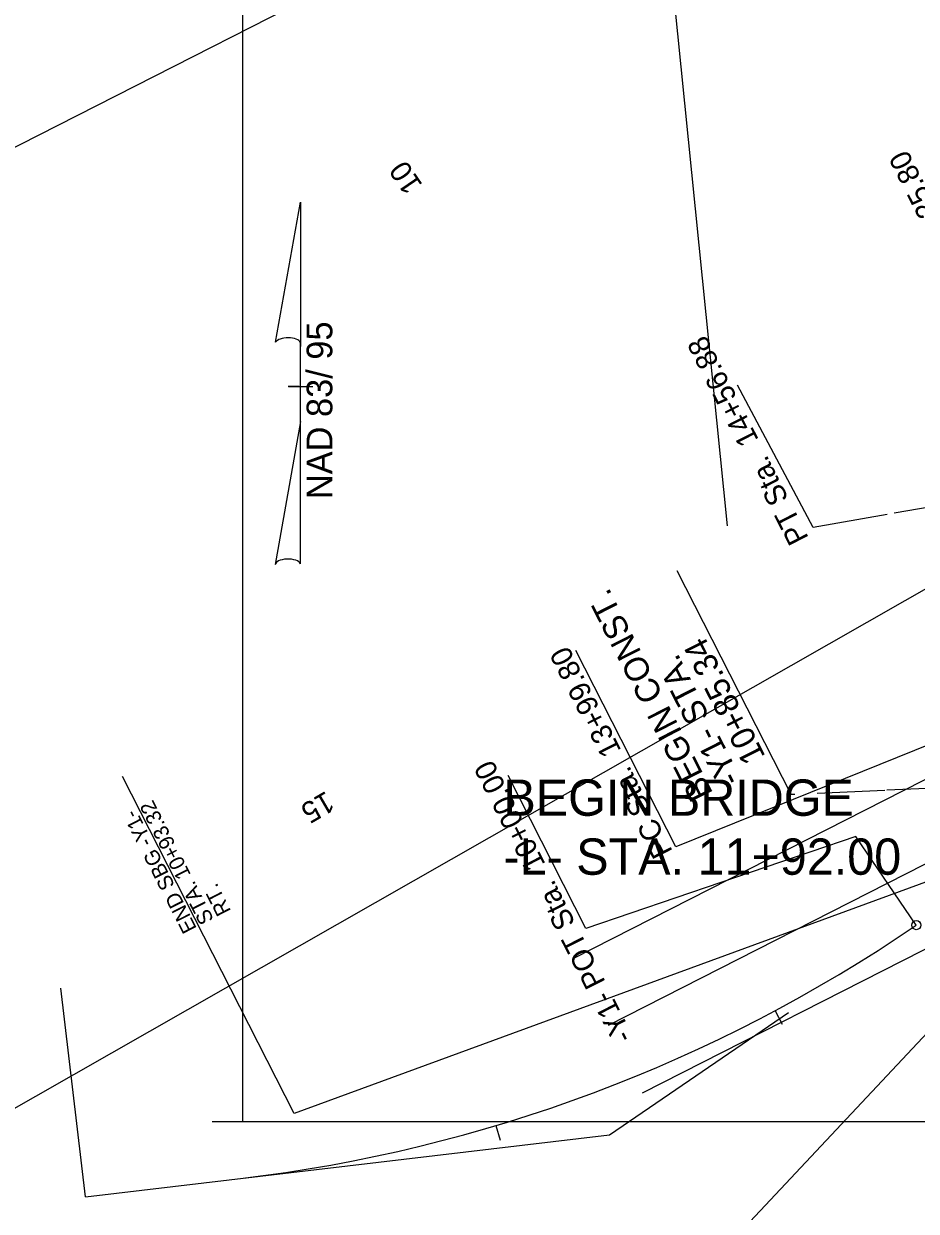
# Model space of a CAD drawing. Extents: x 557583 to 560285, y 513145 to 516544.
# Drawn here: x 558916.3 to 559211.5, y 515428.1 to 515820.8 of the extents above; entities that cross this region are included whole.
import ezdxf

# ---------------------------------------------------------------- set-up
doc = ezdxf.new("R2010")
doc.units = 0
for name, color, linetype in [('Default', 7, 'Continuous'), ('Exist Environmental Wetland Boundary Cogo Comment', 7, 'Continuous'), ('Exist Environmental Wetland Boundary Cogo Point CELL', 7, 'Continuous'), ('Exist Hydro Swamp or Marsh', 7, 'Continuous'), ('Prop Dimension', 7, 'Continuous'), ('Prop DSN Text', 7, 'Continuous'), ('Prop North Arrow NAD83 for Plan Sheets CELL', 7, 'Continuous'), ('Scratch_Level_2', 7, 'Continuous'), ('Scratch_Level_3', 7, 'Continuous'), ('Scratch_Level_4', 7, 'Continuous')]:
    doc.layers.add(name, color=color, linetype=linetype)

msp = doc.modelspace()

# ---------------------------------------------------------------- linework, layer by layer
at = {"layer": 'Default'}
for p, q in [((558988.6, 515880.54), (558988.6, 515457.65)), ((559389.28, 515457.65), (558978.6, 515457.65))]:
    msp.add_line(p, q, dxfattribs=at)
at = {"layer": 'Exist Environmental Wetland Boundary Cogo Point CELL'}
for p, q in [((559177.37, 515654.26), (559152.34, 515701.35)), ((559292.5, 515674.42), (559204.18, 515658.96)), ((559201.9, 515658.56), (559177.37, 515654.26)), ((559131.94, 515548.67), (559098.88, 515613.6)), ((559313.36, 515591.99), (559124.03, 515390.09)), ((559216.64, 515582.81), (559170.76, 515564.32)), ((559102.25, 515521.61), (559076.5, 515572.18)), ((559170.76, 515564.32), (559131.94, 515548.67)), ((559191.49, 515552), (559102.25, 515521.61)), ((559211.5, 515522.74), (559191.49, 515552))]:
    msp.add_line(p, q, dxfattribs=at)
msp.add_circle((559211.5, 515522.74), 1.5, dxfattribs=at)
at = {"layer": 'Exist Hydro Swamp or Marsh'}
for p, q in [((559164.78, 515494.42), (559167.13, 515490.01)), ((559072.45, 515456.44), (559073.88, 515451.65))]:
    msp.add_line(p, q, dxfattribs=at)
at = {"layer": 'Prop Dimension'}
for p, q in [((559170.11, 515565.93), (559132.44, 515639.92)), ((559005.69, 515460.4), (558948.91, 515571.93)), ((559281.95, 515570.9), (559201.81, 515567.34)), ((559294.76, 515566.31), (559005.69, 515460.4)), ((559171.31, 515565.98), (559170.11, 515565.93)), ((559201.15, 515567.31), (559178.67, 515566.31))]:
    msp.add_line(p, q, dxfattribs=at)
at = {"layer": 'Prop DSN Text'}
msp.add_lwpolyline([(558879.66, 516196.55), (559055, 515852.15), (558908.44, 515777.53), (558733.09, 516121.93)], close=True, dxfattribs=at)
at = {"layer": 'Prop North Arrow NAD83 for Plan Sheets CELL'}
for p, q in [((558999.57, 515715.52), (559007.77, 515761.87)), ((559007.82, 515761.87), (559007.77, 515761.87)), ((559007.82, 515761.87), (559007.77, 515761.87)), ((559007.82, 515761.87), (559007.82, 515714.07)), ((559007.82, 515689.27), (559007.82, 515715.47)), ((559007.82, 515714.07), (559007.82, 515715.42)), ((559003.82, 515700.87), (559003.77, 515700.87)), ((559007.37, 515700.87), (559003.82, 515700.87)), ((559003.87, 515700.87), (559011.87, 515700.87)), ((559007.82, 515689.27), (558999.47, 515642.02)), ((559007.87, 515642.22), (559007.82, 515689.27))]:
    msp.add_line(p, q, dxfattribs=at)
for centre, start_param, end_param in [((559003.71, 515715.02), 0.216388, 2.908219), ((559003.71, 515641.85), 0.201328, 3.141593)]:
    msp.add_ellipse(centre, major_axis=(4.23, -0.03), ratio=0.461098, start_param=start_param, end_param=end_param, dxfattribs=at)
at = {"layer": 'Scratch_Level_2'}
for p, q in [((559098.28, 515511.79), (559543.81, 515738.73)), ((559555.17, 515716.41), (559109.6, 515489.55)), ((559120.94, 515467.27), (559566.52, 515694.13))]:
    msp.add_line(p, q, dxfattribs=at)
at = {"layer": 'Scratch_Level_3'}
for p, q in [((559129.15, 515850.4), (559148.98, 515654.78)), ((558936.73, 515432.92), (558928.59, 515501.92)), ((559110.01, 515453.37), (559169.21, 515493.83)), ((558936.73, 515432.92), (559110.01, 515453.37))]:
    msp.add_line(p, q, dxfattribs=at)
msp.add_arc((558929.34, 515935.52), 500, 276.7291, 304.3554, dxfattribs=at)
at = {"layer": 'Scratch_Level_4'}
msp.add_line((559394.6, 515736.6), (558806.81, 515401.49), dxfattribs=at)

# ---------------------------------------------------------------- texts
at = {"layer": 'Default'}
for s, p in [('BEGIN BRIDGE', (559074.95, 515558.9)), ('-L- STA. 11+92.00', (559074.95, 515539.4))]:
    msp.add_text(s, height=12, rotation=360, dxfattribs=at).set_placement(p)
at = {"layer": 'Exist Environmental Wetland Boundary Cogo Comment'}
for s, rotation, p in [('10', 124.3572, (559048.39, 515767.54)), ('15', 210.2524, (559016.3, 515567.3))]:
    msp.add_text(s, height=7, rotation=rotation, dxfattribs=at).set_placement(p)
at = {"layer": 'Exist Environmental Wetland Boundary Cogo Point CELL'}
for s, p in [('POT Sta.  11+25.80', (559246.07, 515705.58)), ('PT Sta.  14+56.88', (559176.04, 515650.75)), ('PC Sta.  13+99.80', (559131.04, 515547.1)), ('-Y1- POT Sta.  10+00.00', (559118.03, 515485.84))]:
    msp.add_text(s, height=7, rotation=116.9819, dxfattribs=at).set_placement(p)
at = {"layer": 'Prop DSN Text'}
for s, height, rotation, p in [('BEGIN CONST.', 8, 116.9819, (559144.41, 515566.33)), (' 10+85.34', 8, 116.9819, (559163.1, 515575.84)), ('-Y1- STA.', 8, 116.9819, (559153.76, 515571.08)), ('STA. 10+93.32', 5, 117.0233, (558979.27, 515524.53)), ('END SBG -Y1-', 5, 117.0233, (558973.63, 515521.65)), ('RT.', 5, 117.0233, (558984.92, 515527.41))]:
    msp.add_text(s, height=height, rotation=rotation, dxfattribs=at).set_placement(p)
at = {"layer": 'Prop North Arrow NAD83 for Plan Sheets CELL'}
msp.add_text('NAD 83/ 95', height=8.5, rotation=90, dxfattribs=at).set_placement((559018.34, 515663.62))

doc.saveas('drawing.dxf')
